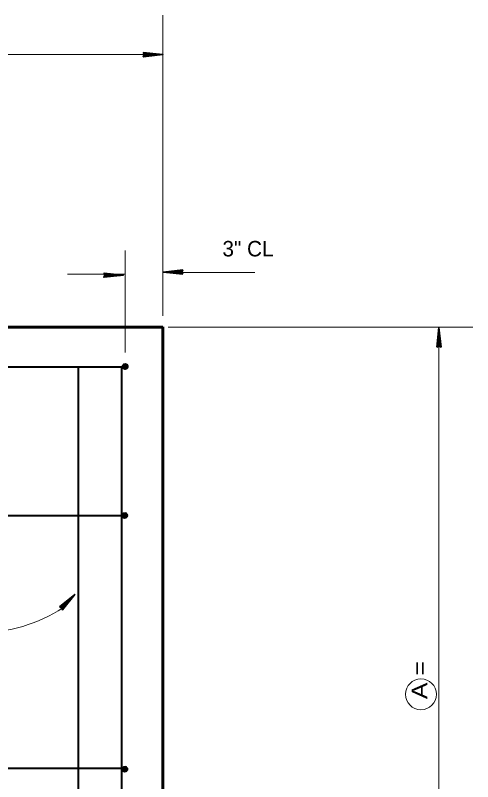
# Model space of a CAD drawing. Extents: x 3.64 to 6.84, y -0.8 to 1.19.
# Drawn here: x 4.5316 to 4.7778, y 0.03 to 0.4424 of the extents above; entities that cross this region are included whole.
import ezdxf

# ---------------------------------------------------------------- set-up
doc = ezdxf.new("R2010")
doc.units = 0
doc.header["$LTSCALE"] = 0.0033
doc.layers.add('1', color=7, linetype='Continuous', lineweight=40)

msp = doc.modelspace()

# ---------------------------------------------------------------- linework, layer by layer
at = {"layer": '1', "lineweight": 13}
for p, q in [((4.611083, 0.280667), (4.611083, 0.442417)), ((4.590667, 0.260917), (4.590667, 0.315833)), ((4.611083, 0.307917), (4.611083, 0.30825)), ((4.611083, 0.307917), (4.611167, 0.307917)), ((4.559667, 0.303167), (4.590583, 0.303167)), ((4.62175, 0.304083), (4.6605, 0.304083)), ((4.613917, 0.274583), (4.77775, 0.274583)), ((4.759583, 0.27275), (4.759583, -0.142083))]:
    msp.add_line(p, q, dxfattribs=at)
at = {"layer": '1', "lineweight": 35}
for p, q in [((4.600417, 0.42125), (4.611, 0.42125)), ((4.600583, 0.420583), (4.607917, 0.421333)), ((4.600667, 0.42225), (4.6085, 0.421333)), ((4.600667, 0.42225), (4.6085, 0.421333)), ((4.600667, 0.422167), (4.6085, 0.421333)), ((4.600667, 0.422083), (4.6085, 0.42125)), ((4.600667, 0.422083), (4.6085, 0.421083)), ((4.600667, 0.420417), (4.608, 0.42125)), ((4.600667, 0.420333), (4.608, 0.421083)), ((4.600667, 0.420167), (4.608, 0.421)), ((4.6215, 0.305333), (4.614167, 0.3045)), ((4.579167, 0.302583), (4.58975, 0.302583)), ((4.579333, 0.301917), (4.586667, 0.302667)), ((4.579417, 0.303583), (4.58725, 0.302667)), ((4.579417, 0.303583), (4.58725, 0.302667)), ((4.579417, 0.3035), (4.58725, 0.302667)), ((4.579417, 0.303417), (4.58725, 0.302583)), ((4.579417, 0.303417), (4.58725, 0.302417)), ((4.579417, 0.30175), (4.58675, 0.302583)), ((4.579417, 0.301667), (4.58675, 0.302417)), ((4.579417, 0.3015), (4.58675, 0.302333)), ((4.62175, 0.30425), (4.611167, 0.30425)), ((4.6215, 0.303417), (4.613667, 0.304417)), ((4.6215, 0.303417), (4.613667, 0.30425)), ((4.6215, 0.30325), (4.613667, 0.304167)), ((4.6215, 0.30325), (4.613667, 0.304167)), ((4.6215, 0.303333), (4.613667, 0.304167)), ((4.6215, 0.305167), (4.614167, 0.304417)), ((4.6215, 0.305083), (4.614167, 0.30425)), ((4.621583, 0.304917), (4.61425, 0.304167)), ((4.759583, 0.263833), (4.759583, 0.274417)), ((4.758583, 0.264083), (4.7595, 0.271917)), ((4.758583, 0.264083), (4.7595, 0.271917)), ((4.758667, 0.264083), (4.7595, 0.271917)), ((4.75875, 0.264083), (4.759583, 0.271917)), ((4.75875, 0.264083), (4.75975, 0.271917)), ((4.76025, 0.264), (4.7595, 0.271333)), ((4.760417, 0.264083), (4.759583, 0.271417)), ((4.7605, 0.264083), (4.75975, 0.271417)), ((4.760667, 0.264083), (4.759833, 0.271417)), ((4.5555, 0.124167), (4.56175, 0.129)), ((4.5555, 0.124167), (4.56175, 0.129)), ((4.555583, 0.124083), (4.56175, 0.129)), ((4.555667, 0.124), (4.56175, 0.129)), ((4.555667, 0.124), (4.561917, 0.128833)), ((4.556083, 0.12325), (4.563583, 0.13075)), ((4.556667, 0.122917), (4.561333, 0.128583)), ((4.556833, 0.122833), (4.561417, 0.128583)), ((4.556917, 0.12275), (4.561583, 0.1285)), ((4.557, 0.122667), (4.561583, 0.128417))]:
    msp.add_line(p, q, dxfattribs=at)
at = {"layer": '1', "lineweight": 60}
for p, q in [((4.271, 0.274583), (4.611083, 0.274583)), ((4.611083, 0.274583), (4.611083, 0.27475))]:
    msp.add_line(p, q, dxfattribs=at)
at = {"layer": '1'}
for p, q in [((4.472167, 0.253167), (4.590833, 0.253167)), ((4.588833, 0.253083), (4.588833, -0.05425)), ((4.589583, 0.252667), (4.589667, 0.254167)), ((4.591667, 0.252833), (4.589667, 0.25325)), ((4.591667, 0.25275), (4.589667, 0.253167)), ((4.591667, 0.252667), (4.589667, 0.253)), ((4.591667, 0.252583), (4.589667, 0.252917)), ((4.591583, 0.252417), (4.589667, 0.25275)), ((4.58975, 0.252667), (4.589833, 0.254167)), ((4.59175, 0.253167), (4.58975, 0.253583)), ((4.59175, 0.253083), (4.58975, 0.253417)), ((4.591667, 0.253), (4.58975, 0.253333)), ((4.589833, 0.252667), (4.589917, 0.254167)), ((4.591833, 0.25375), (4.589833, 0.254083)), ((4.591833, 0.2535), (4.589833, 0.253917)), ((4.59175, 0.253333), (4.589833, 0.25375)), ((4.59175, 0.25325), (4.589833, 0.253667)), ((4.591917, 0.254), (4.589917, 0.254333)), ((4.591833, 0.253917), (4.589917, 0.25425)), ((4.589917, 0.252667), (4.59, 0.254167)), ((4.591833, 0.253833), (4.589917, 0.254167)), ((4.59, 0.252667), (4.590083, 0.254167)), ((4.590083, 0.252667), (4.590167, 0.254167)), ((4.590167, 0.252667), (4.59025, 0.254167)), ((4.59025, 0.252667), (4.590333, 0.254167)), ((4.59025, 0.252667), (4.590333, 0.254167)), ((4.590333, 0.252667), (4.5905, 0.254167)), ((4.5905, 0.252667), (4.590667, 0.254167)), ((4.590667, 0.252583), (4.59075, 0.254083)), ((4.59075, 0.252583), (4.590833, 0.254083)), ((4.590833, 0.252583), (4.590917, 0.254083)), ((4.590917, 0.252583), (4.591, 0.254083)), ((4.591, 0.252583), (4.591083, 0.254083)), ((4.591083, 0.252583), (4.591167, 0.254083)), ((4.591167, 0.252583), (4.59125, 0.254083)), ((4.591333, 0.252583), (4.591417, 0.254083)), ((4.591417, 0.252583), (4.5915, 0.254083)), ((4.5915, 0.252583), (4.591583, 0.254083)), ((4.591583, 0.252583), (4.591667, 0.254083)), ((4.591667, 0.252583), (4.59175, 0.254083)), ((4.47275, 0.17325), (4.589083, 0.17325)), ((4.5895, 0.174), (4.589417, 0.1725)), ((4.589417, 0.1735), (4.591417, 0.173167)), ((4.589417, 0.173417), (4.591417, 0.173)), ((4.589417, 0.173333), (4.591333, 0.172917)), ((4.589417, 0.17325), (4.591333, 0.172833)), ((4.589583, 0.174), (4.5895, 0.1725)), ((4.5895, 0.174), (4.5915, 0.173667)), ((4.5895, 0.173917), (4.5915, 0.173583)), ((4.5895, 0.173833), (4.5915, 0.173417)), ((4.5895, 0.17375), (4.5915, 0.173333)), ((4.5895, 0.173583), (4.591417, 0.17325)), ((4.589583, 0.174167), (4.5915, 0.173833)), ((4.589667, 0.174), (4.589583, 0.1725)), ((4.58975, 0.174), (4.589667, 0.1725)), ((4.589833, 0.174), (4.58975, 0.1725)), ((4.59, 0.174), (4.589917, 0.1725)), ((4.590083, 0.174), (4.59, 0.1725)), ((4.590167, 0.174), (4.590083, 0.1725)), ((4.59025, 0.174), (4.590167, 0.1725)), ((4.590333, 0.174), (4.59025, 0.1725)), ((4.590417, 0.174), (4.590333, 0.1725)), ((4.5905, 0.174), (4.590417, 0.1725)), ((4.590667, 0.173917), (4.5905, 0.172417)), ((4.590833, 0.173917), (4.590667, 0.172417)), ((4.590917, 0.173917), (4.590833, 0.172417)), ((4.590917, 0.173917), (4.590833, 0.172417)), ((4.591, 0.173917), (4.590917, 0.172417)), ((4.591083, 0.173917), (4.591, 0.172417)), ((4.591167, 0.173917), (4.591083, 0.172417)), ((4.59125, 0.173917), (4.591167, 0.172417)), ((4.591333, 0.173917), (4.59125, 0.172417)), ((4.591417, 0.173917), (4.591333, 0.172417)), ((4.591583, 0.173917), (4.5915, 0.172417)), ((4.58925, 0.172583), (4.59125, 0.17225)), ((4.589333, 0.173083), (4.591333, 0.172667)), ((4.589333, 0.172833), (4.591333, 0.1725)), ((4.589333, 0.17275), (4.59125, 0.172417)), ((4.589333, 0.172667), (4.59125, 0.172333)), ((4.4735, 0.03725), (4.589083, 0.03725)), ((4.589583, 0.0375), (4.5895, 0.036)), ((4.589667, 0.0375), (4.589583, 0.036)), ((4.589583, 0.0375), (4.591583, 0.037167)), ((4.589583, 0.037417), (4.591583, 0.037083)), ((4.589583, 0.037333), (4.591583, 0.036917)), ((4.589583, 0.03725), (4.591583, 0.036833)), ((4.589667, 0.037667), (4.591583, 0.037333)), ((4.58975, 0.0375), (4.589667, 0.036)), ((4.589833, 0.0375), (4.58975, 0.036)), ((4.589917, 0.0375), (4.589833, 0.036)), ((4.590083, 0.0375), (4.59, 0.036)), ((4.590167, 0.0375), (4.590083, 0.036)), ((4.59025, 0.0375), (4.590167, 0.036)), ((4.590333, 0.0375), (4.59025, 0.036)), ((4.590417, 0.0375), (4.590333, 0.036)), ((4.5905, 0.0375), (4.590417, 0.036)), ((4.590583, 0.0375), (4.5905, 0.036)), ((4.59075, 0.037417), (4.590583, 0.035917)), ((4.590917, 0.037417), (4.59075, 0.035917)), ((4.591, 0.037417), (4.590917, 0.035917)), ((4.591, 0.037417), (4.590917, 0.035917)), ((4.591083, 0.037417), (4.591, 0.035917)), ((4.591167, 0.037417), (4.591083, 0.035917)), ((4.59125, 0.037417), (4.591167, 0.035917)), ((4.591333, 0.037417), (4.59125, 0.035917)), ((4.591417, 0.037417), (4.591333, 0.035917)), ((4.5915, 0.037417), (4.591417, 0.035917)), ((4.591667, 0.037417), (4.591583, 0.035917)), ((4.589333, 0.036083), (4.591333, 0.03575)), ((4.589417, 0.036583), (4.591417, 0.036167)), ((4.589417, 0.036333), (4.591417, 0.036)), ((4.589417, 0.03625), (4.591333, 0.035917)), ((4.589417, 0.036167), (4.591333, 0.035833)), ((4.5895, 0.037), (4.5915, 0.036667)), ((4.5895, 0.036917), (4.5915, 0.0365)), ((4.5895, 0.036833), (4.591417, 0.036417)), ((4.5895, 0.03675), (4.591417, 0.036333)), ((4.589583, 0.037083), (4.5915, 0.03675))]:
    msp.add_line(p, q, dxfattribs=at)
at = {"layer": '1', "lineweight": 13}
msp.add_lwpolyline([(4.027083, 0.42125), (4.329917, 0.42125), (4.610417, 0.42125)], dxfattribs=at)
at = {"layer": '1', "lineweight": 35}
for points in [[(4.600417, 0.422333), (4.611, 0.42125), (4.600417, 0.420083), (4.601, 0.42125)], [(4.601167, 0.421333), (4.605833, 0.421417), (4.605833, 0.421333), (4.604917, 0.421333), (4.601167, 0.421417), (4.604167, 0.4215), (4.601, 0.421583), (4.60325, 0.421667), (4.601, 0.42175), (4.6045, 0.4215), (4.609167, 0.421333), (4.60825, 0.421083), (4.6095, 0.421083), (4.601167, 0.421083), (4.603583, 0.420917), (4.601, 0.420917), (4.606333, 0.421333), (4.601, 0.420667)], [(4.62175, 0.303167), (4.611167, 0.30425), (4.62175, 0.305417), (4.621167, 0.30425)], [(4.579167, 0.303667), (4.58975, 0.302583), (4.579167, 0.301417), (4.57975, 0.302583)], [(4.579917, 0.302667), (4.584583, 0.30275), (4.584583, 0.302667), (4.583667, 0.302667), (4.579917, 0.30275), (4.582917, 0.302833), (4.57975, 0.302917), (4.582, 0.303), (4.57975, 0.303083), (4.58325, 0.302833), (4.587917, 0.302667), (4.587, 0.302417), (4.58825, 0.302417), (4.579917, 0.302417), (4.582333, 0.30225), (4.57975, 0.30225), (4.585083, 0.302667), (4.57975, 0.302)], [(4.621, 0.304167), (4.616333, 0.304083), (4.616333, 0.304167), (4.61725, 0.304167), (4.621, 0.304083), (4.618, 0.304), (4.621167, 0.303917), (4.618917, 0.303833), (4.621167, 0.30375), (4.617667, 0.304), (4.613, 0.304167), (4.613917, 0.304417), (4.612667, 0.304417), (4.621, 0.304417), (4.618583, 0.304583), (4.621167, 0.304583), (4.615833, 0.304167), (4.621167, 0.304833)], [(4.7585, 0.263833), (4.759583, 0.274417), (4.76075, 0.263833), (4.759583, 0.264417)], [(4.7595, 0.264583), (4.759417, 0.26925), (4.7595, 0.26925), (4.7595, 0.268333), (4.759417, 0.264583), (4.759333, 0.267583), (4.75925, 0.264417), (4.759167, 0.266667), (4.759083, 0.264417), (4.759333, 0.267917), (4.7595, 0.272583), (4.75975, 0.271667), (4.75975, 0.272917), (4.75975, 0.264583), (4.759917, 0.267), (4.759917, 0.264417), (4.7595, 0.26975), (4.760167, 0.264417)], [(4.555333, 0.124), (4.563583, 0.13075), (4.556917, 0.122417), (4.5565, 0.123667)], [(4.5565, 0.123833), (4.55975, 0.12725), (4.559833, 0.127167), (4.559167, 0.1265), (4.5565, 0.123917), (4.5585, 0.126083), (4.55625, 0.123917), (4.55775, 0.125583), (4.556083, 0.124), (4.55875, 0.126333), (4.562167, 0.1295), (4.56175, 0.128667), (4.562583, 0.129583), (4.55675, 0.123667), (4.5585, 0.12525), (4.55675, 0.123417), (4.560167, 0.1275), (4.556917, 0.12325)]]:
    msp.add_lwpolyline(points, close=True, dxfattribs=at)
for points in [[(4.601167, 0.421333), (4.60075, 0.422083), (4.601, 0.421833), (4.601167, 0.4215), (4.601417, 0.421583), (4.60125, 0.421917), (4.601083, 0.421167), (4.600917, 0.420667), (4.600667, 0.42025)], [(4.621, 0.304167), (4.621417, 0.303417), (4.621167, 0.303667), (4.621, 0.304), (4.62075, 0.303917), (4.620917, 0.303583), (4.621083, 0.304333), (4.62125, 0.304833), (4.6215, 0.30525)], [(4.579917, 0.302667), (4.5795, 0.303417), (4.57975, 0.303167), (4.579917, 0.302833), (4.580167, 0.302917), (4.58, 0.30325), (4.579833, 0.3025), (4.579667, 0.302), (4.579417, 0.301583)], [(4.7595, 0.264583), (4.75875, 0.264167), (4.759, 0.264417), (4.759333, 0.264583), (4.75925, 0.264833), (4.758917, 0.264667), (4.759667, 0.2645), (4.760167, 0.264333), (4.760583, 0.264083)], [(4.5565, 0.123833), (4.55575, 0.124083), (4.556083, 0.124083), (4.556417, 0.124), (4.5565, 0.124167), (4.556167, 0.124333), (4.556583, 0.123667), (4.556833, 0.123167), (4.556917, 0.12275)]]:
    msp.add_lwpolyline(points, dxfattribs=at)
at = {"layer": '1', "lineweight": 60}
msp.add_lwpolyline([(4.611083, 0.274583), (4.611083, -0.05875), (4.694417, -0.05875), (4.694417, -0.142083)], dxfattribs=at)
at = {"layer": '1'}
for points in [[(4.565417, 0.253583), (4.565417, -0.00275), (4.5595, -0.008667), (4.5595, -0.054917)], [(4.592083, 0.253417), (4.5895, 0.253083), (4.591833, 0.252583), (4.5895, 0.253667), (4.591917, 0.254083), (4.589917, 0.254417), (4.589917, 0.252333), (4.590833, 0.254667), (4.590583, 0.252083), (4.591583, 0.254417), (4.59125, 0.252083), (4.590417, 0.254667), (4.592, 0.252917), (4.589583, 0.25275), (4.59125, 0.254583), (4.590167, 0.252167), (4.591833, 0.252583), (4.591917, 0.254083), (4.590833, 0.254667), (4.589917, 0.254417), (4.5895, 0.253667), (4.589583, 0.25275), (4.590167, 0.252167), (4.590833, 0.25325), (4.589667, 0.254167), (4.591583, 0.254417), (4.590833, 0.25325), (4.591917, 0.25275), (4.590917, 0.252083), (4.590833, 0.253167), (4.59, 0.254417), (4.592, 0.253167), (4.590667, 0.252833), (4.589917, 0.252333)], [(4.589083, 0.173167), (4.591667, 0.1735), (4.589333, 0.174), (4.591667, 0.172917), (4.58925, 0.1725), (4.59125, 0.172167), (4.59125, 0.17425), (4.590333, 0.171917), (4.590583, 0.1745), (4.589583, 0.172167), (4.589917, 0.1745), (4.59075, 0.171917), (4.589167, 0.173667), (4.591583, 0.173833), (4.589917, 0.172), (4.591, 0.174417), (4.589333, 0.174), (4.58925, 0.1725), (4.590333, 0.171917), (4.59125, 0.172167), (4.591667, 0.172917), (4.591583, 0.173833), (4.591, 0.174417), (4.590333, 0.173333), (4.5915, 0.172417), (4.589583, 0.172167), (4.590333, 0.173333), (4.58925, 0.173833), (4.59025, 0.1745), (4.590333, 0.173417), (4.591167, 0.172167), (4.589167, 0.173417), (4.5905, 0.17375), (4.59125, 0.17425)], [(4.589167, 0.036667), (4.59175, 0.037), (4.589417, 0.0375), (4.59175, 0.036417), (4.589333, 0.036), (4.591333, 0.035667), (4.591333, 0.03775), (4.590417, 0.035417), (4.590667, 0.038), (4.589667, 0.035667), (4.59, 0.038), (4.590833, 0.035417), (4.58925, 0.037167), (4.591667, 0.037333), (4.59, 0.0355), (4.591083, 0.037917), (4.589417, 0.0375), (4.589333, 0.036), (4.590417, 0.035417), (4.591333, 0.035667), (4.59175, 0.036417), (4.591667, 0.037333), (4.591083, 0.037917), (4.590417, 0.036833), (4.591583, 0.035917), (4.589667, 0.035667), (4.590417, 0.036833), (4.589333, 0.037333), (4.590333, 0.038), (4.590417, 0.036917), (4.59125, 0.035667), (4.58925, 0.036917), (4.590583, 0.03725), (4.591333, 0.03775)]]:
    msp.add_lwpolyline(points, dxfattribs=at)
for centre in [(4.59075, 0.253367), (4.590417, 0.173217), (4.5905, 0.036717)]:
    msp.add_circle(centre, 0.00132, dxfattribs=at)
at = {"layer": '1', "lineweight": 13}
msp.add_circle((4.749917, 0.077), 0.008333, dxfattribs=at)
msp.add_arc((4.512085, 0.192659), 0.082492, 269.94116, 303.17307, dxfattribs=at)

# ---------------------------------------------------------------- texts
at = {"layer": '1'}
msp.add_text('3" CL', height=0.008334, dxfattribs=at).set_placement((4.643083, 0.312667))
at = {"layer": '1', "width": 1.2}
msp.add_text('A =      ', height=0.008334, rotation=90, dxfattribs=at).set_placement((4.753333, 0.074417))

doc.saveas('drawing.dxf')
